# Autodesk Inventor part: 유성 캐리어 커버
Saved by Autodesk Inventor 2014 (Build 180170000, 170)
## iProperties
Created: 2026-05
Part Number: 유성 캐리어 커버
Material: 일반
Document SubType Name: Modeling
Designer: dg
Density: 1 g/cm^3
Appearance: 기본값
Author: dg
Author: jhkim
Creation Date: 2026-04-27
Sending System: Autodesk Inventor 2027
Preprocessor: ST-DEVELOPER v20.1
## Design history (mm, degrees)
node "유성 캐리어 커버1"
node "솔리드1"
node "기준1"
